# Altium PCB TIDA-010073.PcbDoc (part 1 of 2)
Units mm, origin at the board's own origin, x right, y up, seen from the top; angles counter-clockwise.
Board outline 68.14 x 25.33 mm, 2 copper layers (Top Layer, Bottom Layer), stack 1.575 mm thick; 47 components, 34 nets, 125 pads, 64 vias.
Unrouted connection lines stored in the file: 4.
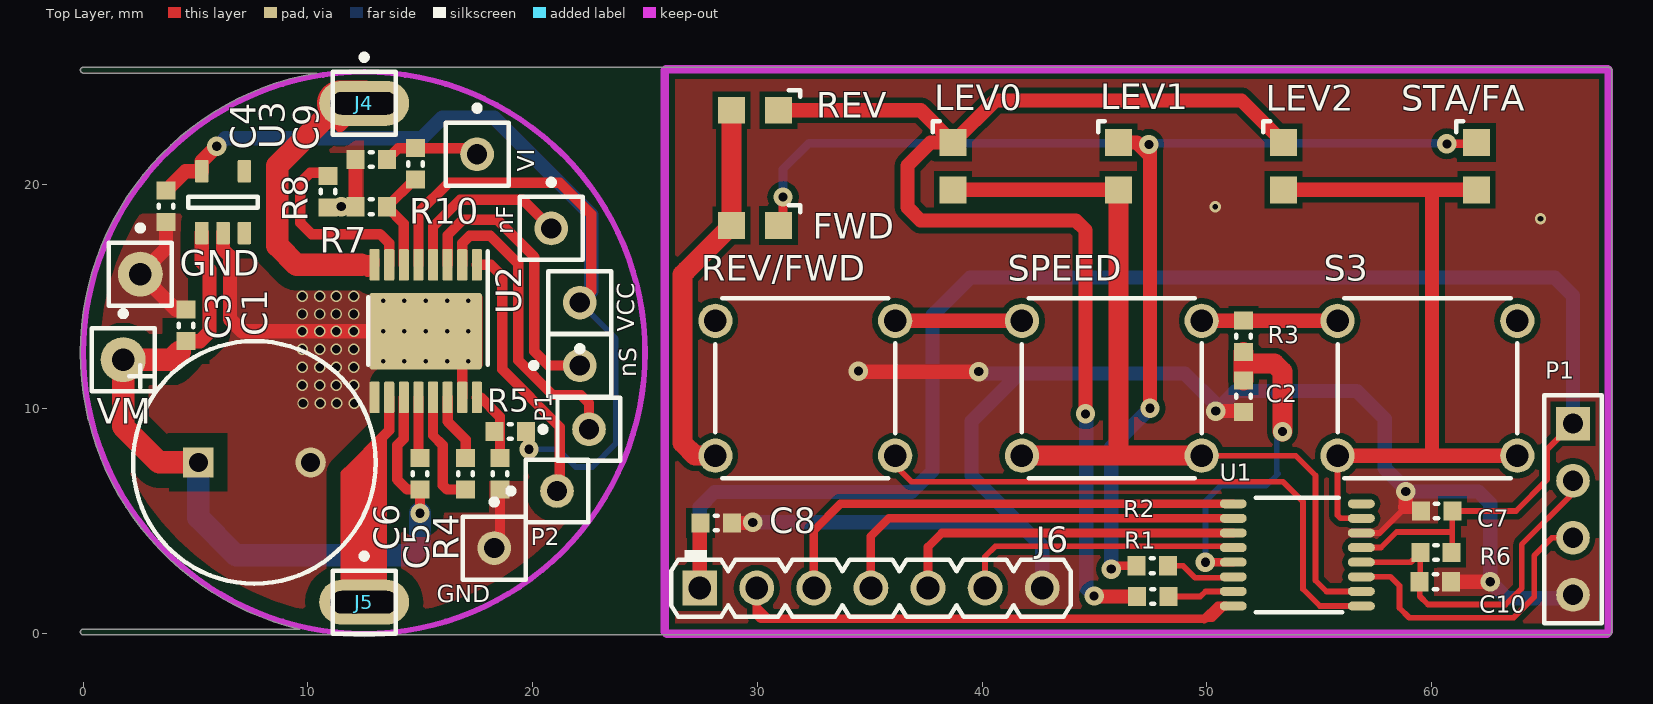
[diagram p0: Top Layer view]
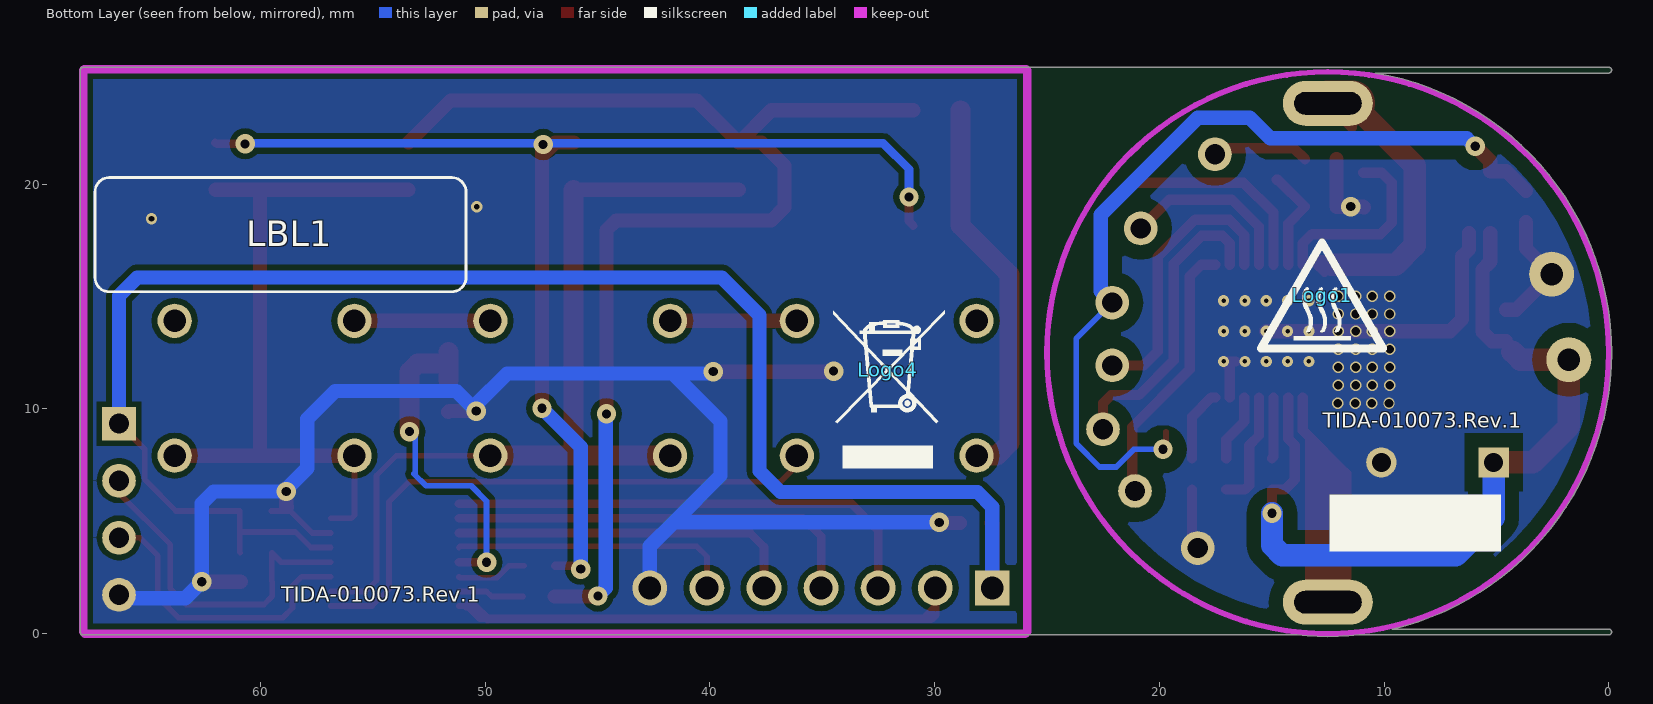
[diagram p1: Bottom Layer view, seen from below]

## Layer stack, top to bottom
Top Solder: solder mask 0.0102, Solder Resist, Dk 3.5
Top Layer: signal copper 0.0356
Dielectric1: core 1.5037, FR-4, Dk 4.8
Bottom Layer: signal copper 0.0356
Bottom Solder: solder mask 0.0102, Solder Resist, Dk 3.5

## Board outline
0,-0.051 cw(c0,0.076) 0,0.204 9.628,0.204 cw(c12.5,12.5) -0.127,12.5 cw(c12.5,12.5) 10.384,24.949 0,24.949 cw(c0,25.076) 0,25.204 67.885,25.204 cw(c67.885,25.076) 68.013,25.076 68.013,0.076 cw(c67.885,0.076) 67.885,-0.051 13.885,-0.051 cw(c12.5,12.5) 12.5,-0.127 cw(c12.5,12.5) 11.115,-0.051

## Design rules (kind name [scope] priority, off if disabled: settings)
AcuteAngle [All] p1: minimum=4.50000000000000E+0001 checktracksonly=FALSE
AssemblyTestPointUsage [All] p1: valid=2
BoardOutlineClearance BoardOutlineClearance_MountingHoles [OnCopper and InComponentClass('Mounting Holes')] p1 off: gap=1.016 ignorepadtopadclearanceinfootprint=FALSE
BoardOutlineClearance BoardOutlineClearance_Poly [OnCopper and IsPoly] p2 off: gap=0.635 ignorepadtopadclearanceinfootprint=FALSE
BoardOutlineClearance [OnCopper and Not InComponentClass('Logo') and not InComponentClass('FiducialMark') and not InRegion(1000,500,4000,800) and not InPoly] p3 off: gap=1.905 ignorepadtopadclearanceinfootprint=FALSE
Clearance Clearance_Keepouts [((IsTrack Or IsArc) And Not InPoly) And IsFree and IsKeepOut vs ((IsTrack Or IsArc) And Not InPoly) And IsFree and IsKeepOut] p1 off: gap=0 ignorepadtopadclearanceinfootprint=FALSE
Clearance Clearance_Poly [InPolygon] p2 off: gap=0.635 ignorepadtopadclearanceinfootprint=FALSE except(0: Arc-Hole Track-Hole SMDPad-Hole THPad-Hole Via-Hole Fill-Hole Poly-Hole Region-Hole Text-Hole)
Clearance Clearance_FiducialMark [IsKeepOut and InComponentClass('FiducialMark') vs IsPad and InComponentClass('FiducialMark')] p3 off: gap=0.381 ignorepadtopadclearanceinfootprint=FALSE
Clearance [All] p4: gap=0.254 ignorepadtopadclearanceinfootprint=FALSE
ComponentClearance ComponentClearance_MountingHoles_FiducialMarks [InComponentClass('Mounting Holes') vs InComponentClass('FiducialMark')] p1: gap=1.27 collisioncheckmode=3 verticalgap=0.254 showdistances=FALSE
ComponentClearance ComponentClearance_Shunt [InComponentClass('Header') vs InComponentClass('Shunt')] p2: gap=0 collisioncheckmode=3 verticalgap=0 showdistances=FALSE
ComponentClearance ComponentClearance_Logo [InComponentClass('Logo')] p3: gap=1.27 collisioncheckmode=3 verticalgap=0.254 showdistances=FALSE
ComponentClearance ComponentClearance_ScrewToNut [(HasFootprint('NY PMS 440 0025 PH')) vs (HasFootprint('Keystone_1902C'))] p4: gap=0.127 collisioncheckmode=3 verticalgap=0.254 showdistances=FALSE
ComponentClearance ComponentClearance_MountingHoles [InComponentClass('Mounting Holes')] p5: gap=6.35 collisioncheckmode=3 verticalgap=2540 showdistances=FALSE
ComponentClearance ComponentClearance_SmallPassives [HasFootprint('0201*') or HasFootprint('0402*') or HasFootprint('0508') or HasFootprint('0603*') or HasFootprint('0612') or HasFootprint('0805*') or HasFootprint('0815*') or HasFootprint('0830*') or HasFootprint('1206*') or HasFootprint('1210*') or HasFootprint('1808*') or HasFootprint('1812*') or HasFootprint('1825*') or HasFootprint('2010*') or HasFootprint('2220*') or HasFootprint('2225*') or HasFootprint('2512*') or HasFootprint('2728*') or HasFootprint('3518*') vs HasFootprint('0201*') or HasFootprint('0402*') or HasFootprint('0508') or HasFootprint('0603*') or HasFootprint('0612') or HasFootprint('0805*') or HasFootprint('0815*') or HasFootprint('0830*') or HasFootprint('1206*') or HasFootprint('1210*') or HasFootprint('1808*') or HasFootprint('1812*') or HasFootprint('1825*') or HasFootprint('2010*') or HasFootprint('2220*') or HasFootprint('2225*') or HasFootprint('2512*') or HasFootprint('2728*') or HasFootprint('3518*')] p6: gap=0.38 collisioncheckmode=3 verticalgap=0.254 showdistances=FALSE
ComponentClearance ComponentClearance_THtoSMT [IsThruComponent vs IsSMTComponent] p7: gap=1.016 collisioncheckmode=3 verticalgap=0.762 showdistances=FALSE
ComponentClearance ComponentClearance_THtoTH [IsThruComponent vs IsThruComponent] p8: gap=0.762 collisioncheckmode=3 verticalgap=0.762 showdistances=FALSE
ComponentClearance [All] p9: gap=0.762 collisioncheckmode=3 verticalgap=0.254 showdistances=FALSE
DiffPairsRouting [All] p1: maxlimit=2.54 minlimit=0.254 mostfreqgap=0.254 toplayer_minwidth=0.381 toplayer_maxwidth=0.381 toplayer_prefwidth=0.381 bottomlayer_minwidth=0.381 bottomlayer_maxwidth=0.381 bottomlayer_prefwidth=0.381 maxuncoupledlength=25.4
FabricationTestPointUsage TestPointUsage [All] p1: valid=2 allowmultiple=FALSE
FabricationTestpoint Testpoint [All] p1: side=3 testpointundercomponent=TRUE minsize=1.016 maxsize=2.54 preferedsize=1.524 minholesize=0 maxholesize=1.016 preferedholesize=0.813 testpointgrid=0.025 allowsidetop=TRUE allowsidebottom=TRUE usegrid=TRUE gridtolerance=0
FanoutControl Fanout_LCC [IsLCC] p1: bgadir=Out bgaviamode=Centered fanoutstyle=Auto fanoutdirection=Alternating viagrid=0.025 // Fanout_LCC (Default Rule)
FanoutControl Fanout_BGA [IsBGA] p2: bgadir=Out bgaviamode=Centered fanoutstyle=Auto fanoutdirection=Alternating viagrid=0.025 // Fanout_BGA (Default Rule)
FanoutControl Fanout_Default [All] p4: bgadir=Out bgaviamode=Centered fanoutstyle=Auto fanoutdirection=Alternating viagrid=0.025 // Fanout_Default (Default Rule)
FanoutControl Fanout_Small [(CompPinCount < 5)] p5: bgadir=Out bgaviamode=Centered fanoutstyle=Auto fanoutdirection=OutThenIn viagrid=0.025 // Fanout_Small (Default Rule)
HoleSize [All] p1: absolutevalues=TRUE maxlimit=6.375 minlimit=0.2 maxpercent=80.000 minpercent=20.000
HoleToHoleClearance [All] p1 off: gap=0.254 allowstackedmicrovias=TRUE
MinimumAnnularRing MinimumAnnularRing_ThermalPadVias [IsVia and InAnyComponent] p1: minimumring=0.15
MinimumAnnularRing [All] p2: minimumring=0.203
MinimumSolderMaskSliver MinimumSolderMaskSliver_Logo [InComponentClass('Logo') vs InComponentClass('Logo')] p1: minsoldermaskwidth=0.018
MinimumSolderMaskSliver [All] p2: minsoldermaskwidth=0.1
PlaneConnect [All] p1: planeconnectstyle=Relief reliefexpansion=0.254 reliefentries=4 reliefconductorwidth=0.254 reliefairgap=0.254
PolygonConnect [All] p1: connectstyle=Direct reliefconductorwidth=0.254 reliefentries=4 polygonreliefangle="90 Angle" airgapwidth=0.254
RoutingVias ThermalPadVias [IsVia and InAnyComponent] p1: holewidth=0.2 width=0.5 viastyle="Through Hole" minholewidth=0.2 minwidth=0.5 maxholewidth=0.33 maxwidth=0.6
RoutingVias [All] p2: holewidth=0.406 width=0.864 viastyle="Through Hole" minholewidth=0.2 minwidth=0.66 maxholewidth=1.016 maxwidth=1.651
SilkToBoardRegionClearance [Not ((IsComment or IsDesignator) And (Hide <> 'False')) and not InRegion(1000,500,4000,800)] p1:
SilkToSilkClearance SilkToSilkClearance_Pb-FreeLogo [(HasFootprint('Pb-Free_Overlay_Medium') OR HasFootprint('Pb-Free_Overlay_Small')) vs (HasFootprint('Pb-Free_Overlay_Medium') OR HasFootprint('Pb-Free_Overlay_Small'))] p1: silktosilkclearance=0
SilkToSilkClearance [All] p2: silktosilkclearance=0.102
SilkToSolderMaskClearance SilkToComponentPadClearance [(IsPad or IsFill or IsRegion) and InAnycomponent] p1: minsilkscreentomaskgap=0.127 clearancetoexposedcopper=TRUE
SilkToSolderMaskClearance "Silk to Solder Mask Opening" [All] p2: minsilkscreentomaskgap=0.102 clearancetoexposedcopper=FALSE
SolderMaskExpansion [All] p1: expansion=0.05
UnRoutedNet [All] p1 off:
UnpouredPolygon [All] p1 off:
Width [All] p1: maxlimit=2.54 minlimit=0.152 preferedwidth=0.254 checkconnectedcopper=TRUE
12 further rules are at their usual default settings.

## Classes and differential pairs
component class Header: J6
component class TIDA-010073_Page1: C1 C2 C3 C4 C5 C6 C7 C8 C9 C10 FWD GND J4 J5 J6 LEV0 LEV1 LEV2 nF nS P1 P2 R1 R2 R3 R4 R6 R7 R8 R10 REV REV/FWD S3 SPEED STA/FA U1 U2 U3 VCC VI VM
component class Label: LBL1
component class TIDA-010073_EVM_Hardware: LBL1 Logo1 Logo4

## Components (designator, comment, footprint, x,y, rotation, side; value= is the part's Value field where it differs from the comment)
C1 "UBT1H101MPD1TD" BT_1000x1250 7.62,7.62 r0 top value=100uF
C2 "C0603X104K8RACTU" 0603L 51.638,10.566 r270 top value=0.1uF
C3 "C1608X7R1H104K080AA" 0603L 4.572,13.716 r90 top value=0.1uF
C4 "GRM188R71A225KE15D" 0603L 3.683,19.013 r270 top value=2.2uF
C5 "885012206091" 0603L 17.018,7.112 r90 top value=0.022uF
C6 "C1608X7R1H104K080AA" 0603L 14.986,7.112 r90 top value=0.1uF
C7 "C1608X7R1H104K080AA" 0603L 60.223,5.461 r180 top value=0.1uF
C8 "885012206026" 0603L 28.169,4.928 r0 top value=1uF
C9 "C1608X7R1H104K080AA" 0603L 12.813,21.107 r180 top value=0.1uF
C10 "C0603C471K5RACTU" 0603L 60.173,2.311 r0 top value=470pF
FWD "SM0805GCL" SM0805_Green 29.896,18.161 r0 top value=Green (schematic designator D2)
GND "GND" PIN1#1 2.54,16.002 r0 top (schematic designator J3)
GND "VM" PIN1#2 18.288,3.81 r0 top (schematic designator J12)
J4 "OUT1" PIN1#3 12.5,23.6 r0 top
J5 "OUT2" PIN1#3 12.5,1.4 r0 top
J6 "PBC07SFAN" Sullins_xxC07SFAN 35.052,2.032 r0 top
LBL1 "THT-14-423-10" Label_650x200 59.106,17.755 r180 bottom
LEV0 "SM0805GCL" SM0805_Green 38.71,20.803 r90 top value=Green (schematic designator D3)
LEV1 "SM0805GCL" SM0805_Green 46.063,20.803 r90 top value=Green (schematic designator D4)
LEV2 "SM0805GCL" SM0805_Green 53.416,20.803 r90 top value=Green (schematic designator D5)
Logo1 "CAUTION HOT SURFACE" IEC_HotSurface_Small 12.755,15.062 r180 bottom (schematic designator LOGO1)
Logo4 "WEEE logo" WEEE_Minimum 32.078,11.735 r180 bottom
nF "VM" PIN1#2 20.828,18.034 r0 top (schematic designator J9)
nS "VM" PIN1#2 22.098,11.938 r90 top (schematic designator J8)
P1 "VM" PIN1#2 22.504,9.093 r90 top (schematic designator J11)
P1 "Header 4" HDR1X4 66.294,9.347 r270 top
P2 "VM" PIN1#2 21.082,6.35 r90 top (schematic designator J10)
R1 "CRCW0603330RJNEA" 0603L 47.6,1.651 r180 top value=330
R2 "CRCW0603330RJNEA" 0603L 47.574,3.023 r180 top value=330
R3 "CRCW06031K00JNEA" 0603L 51.638,13.233 r270 top value=1.0k
R4 "ERJ-3GEY0R00V" 0603L 18.542,7.112 r90 top value=0
R5 "ERJ-3GEY0R00V" 0603L 18.999,8.992 r180 top value=0
R6 "CRCW060347K0JNEA" 0603L 60.198,3.607 r180 top value=47k
R7 "ERJ-3GEY0R00V" 0603L 12.816,18.999 r0 top value=0
R8 "ERJ-3GEY0R00V" 0603L 10.897,19.674 r90 top value=0
R10 "RC0603JR-072K2L" 0603L 14.783,20.904 r90 top value=2.2k
REV "SM0805GCL" SM0805_Green 29.896,23.292 r0 top value=Green (schematic designator D1)
REV/FWD "ESE-20C341" SW_ESE20C3 32.131,10.922 r0 top (schematic designator S1)
S3 "ESE-20C341" SW_ESE20C3 59.817,10.922 r0 top
SPEED "ESE-20C341" SW_ESE20C3 45.771,10.922 r0 top (schematic designator S2)
STA/FA "SM0805GCL" SM0805_Green 62.001,20.803 r90 top value=Green (schematic designator D6)
U1 "MSP430FR2111IPW16R" PW0016A_L 54.026,3.505 r180 top
U2 "DRV8876PWPR" PWP0016J_N 15.24,13.462 r270 top
U3 "TPS70933DBVR" DBV0005A_N 6.223,19.202 r90 top
VCC "VM" PIN1#2 22.098,14.732 r180 top (schematic designator J1)
VI "VM" PIN1#2 17.526,21.336 r0 top (schematic designator J7)
VM "VM" PIN1#1 1.778,12.192 r0 top (schematic designator J2)

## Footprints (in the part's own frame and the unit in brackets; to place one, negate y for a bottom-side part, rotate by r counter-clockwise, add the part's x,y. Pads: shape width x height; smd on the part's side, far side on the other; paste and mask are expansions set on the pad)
0603L [mm] "0603 from SM-752 data"
  rect 0.8x0.85 smd: 1(-0.7,0) 2(0.7,0)
  silkscreen extent -0.07,-0.33 0.07,0.33, body extent -0.87,-0.47 0.87,0.47, height 1
BT_1000x1250 [mm] "Nichicon"
  rect 1.35x1.35 hole 0.85 paste+0: 1(-2.5,0)
  round 1.35 hole 0.85 paste+0: 2(2.5,0)
  silkscreen extent -5.58,-5.4 5.4,5.4, body extent -5.36,-5.39 5.39,5.39, height 14.51
DBV0005A_N [mm] "SOT23, 5-Leads, Body 2.9x1.6mm, Pitch 0.95mm, Lead Span 2.8mm, IPC Medium Density"
  rrect17% 1x0.6 smd: 1(-1.375,0.95) 2(-1.375,0) 3(-1.375,-0.95) 4(1.375,-0.95) 5(1.375,0.95)
  silkscreen extent -0.25,-1.55 0.25,1.55, body extent -1.42,-1.46 1.42,1.46, height 1.09
HDR1X4 [mm] "Connector; Header; 4 Position"
  rect 1.5x1.5 hole 0.9: 1(0,0)
  round 1.5 hole 0.9: 2(2.54,0) 3(5.08,0) 4(7.62,0)
  silkscreen extent -1.27,-1.27 8.89,1.27
IEC_HotSurface_Small [mm]
  silkscreen extent -2.72,-2.36 2.72,2.35
Label_650x200 [mil] "Thermal Transfer Label"
  round 1 on Mech14: 0(0,0)
  silkscreen extent -325,-100 325,100, body extent -325,-100 325,100, height 1
PIN1#1 [mm] "Connector; Plug"
  round 2 hole 1: 1(0,0)
  silkscreen extent -1.4,-1.4 1.4,2.17
PIN1#2 [mm] "Connector; Plug"
  round 1.5 hole 0.9: 1(0,0)
  silkscreen extent -1.4,-1.4 1.4,2.17
PIN1#3 [mm] "Connector; Plug"
  oval 4x2 hole 1 slot 3 at 0 deg: 1(0,0)
  silkscreen extent -1.4,-1.4 1.4,2.17
PW0016A_L [mm] "TSOP, 16-Leads, Body 5x4.4mm, Pitch 0.65mm, IPC High Density"
  oval 1.2x0.4 smd: 1(-2.85,2.275) 2(-2.85,1.625) 3(-2.85,0.975) 4(-2.85,0.325) 5(-2.85,-0.325) 6(-2.85,-0.975) 7(-2.85,-1.625) 8(-2.85,-2.275) 9(2.85,-2.275) 10(2.85,-1.625) 11(2.85,-0.975) 12(2.85,-0.325) 13(2.85,0.325) 14(2.85,0.975) 15(2.85,1.625) 16(2.85,2.275)
  silkscreen extent -2,-2.55 1.85,2.55, body extent -3.21,-2.5 3.21,2.5, height 1
PWP0016J_N [mm] "TSOP, 16-Leads, Body 5x4.4mm, Pitch 0.65mm, Exposed Pad, IPC Medium Density"
  rrect22% 1.4x0.45 smd: 1(-2.95,2.275) 2(-2.95,1.625) 3(-2.95,0.975) 4(-2.95,0.325) 5(-2.95,-0.325) 6(-2.95,-0.975) 7(-2.95,-1.625) 8(-2.95,-2.275) 9(2.95,-2.275) 10(2.95,-1.625) 11(2.95,-0.975) 12(2.95,-0.325) 13(2.95,0.325) 14(2.95,0.975) 15(2.95,1.625) 16(2.95,2.275)
  rrect6% 3.4x5 smd paste-1.7 mask-1.7: 17(0,0)
  rrect4% 2.46x3.55 on Top Paste: 17(0,0)
  rrect4% 2.46x3.55 on Top Solder: 17(0,0)
  silkscreen extent -3.55,-2.55 1.5,2.75, body extent -3.2,-2.5 3.2,2.5, height 1.13
SM0805_Green [mm] "Bivar"
  rect 1.2x1.2 smd: 1(-1.05,0) 2(1.05,0)
  silkscreen extent 1.5,0.6 2,0.9, body extent -1.13,-0.75 1.13,0.75, height 1.07
Sullins_xxC07SFAN [mm] "Header, 2.54 mm, 7x1, TH"
  rect 1.55x1.55 hole 1.016: 1(-7.62,0)
  round 1.55 hole 1.016: 2(-5.08,0) 3(-2.54,0) 4(0,0) 5(2.54,0) 6(5.08,0) 7(7.62,0)
  silkscreen extent -8.89,-1.28 8.89,1.7, body extent -8.89,-1.27 8.89,1.27, height 10.62
SW_ESE20C3 [mm] "Panasonic recommended land pattern  00 Sept 2010"
  round 1.524 hole 1: A(-4,3) B(-4,-3) C(4,3) D(4,-3)
  silkscreen extent -4,-4 4,4, body extent -3.9,-3.95 3.9,3.95, height 12.5
WEEE_Minimum [mm] "WEEElie bin"
  silkscreen extent -2.42,-4.38 2.52,2.65

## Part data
C1: library part CMP-0009918-2, "CAP, AL, 100 uF, 50 V, +/- 20%, TH", Cap_Case=10x12.5mm, Manufacturer=Nichicon, Supplier Part Number 1=493-4508-1-ND, Tolerance_%=20%, Value1=Unknown, Value2=50V, ValueDisplayed=100uF
C2: "CAP, CERM, 0.1 ¦ÌF, 10 V,+/- 10%, X7R, 0603", Cap_Case=0603, Manufacturer=Kemet, Supplier Part Number 1=399-5343-1-ND, TempCo=X7R, Tolerance_%=10, Value2=10V, ValueDisplayed=0.1µF
C3 C6 C7 C9: library part CMP-0007044-5, "CAP, CERM, 0.1 uF, 50 V, +/- 10%, X7R, 0603", Cap_Case=0603, Manufacturer=TDK, Supplier Part Number 1=445-1314-1-ND, TempCo=X7R, Tolerance_%=10%, Value1="0.0296 ohm", Value2=50V, ValueDisplayed=0.1uF
C4: "CAP, CERM, 2.2 ¦ÌF, 10 V,+/- 10%, X7R, 0603", Cap_Case=0603, Manufacturer=MuRata, Supplier Part Number 1=490-4520-1-ND, TempCo=X7R, Tolerance_%=10, Value1="0.009 ohm", Value2=10V, ValueDisplayed=2.2µF
C5: library part CMP-0006836-4, "CAP, CERM, 0.022 uF, 50 V, +/- 10%, X7R, 0603", Cap_Case=0603, Manufacturer="Wurth Elektronik", TempCo=X7R, Tolerance_%=10%, Value1=Unknown, Value2=50V, ValueDisplayed=0.022uF
C8: library part CMP-0064932-4, "CAP, CERM, 1 uF, 10 V,+/- 10%, X7R, 0603", Cap_Case=0603, Manufacturer="Wurth Elektronik", Supplier Part Number 1=732-7945-1-ND, TempCo=X7R, Tolerance_%=10%, Value1=Unknown, Value2=10V, ValueDisplayed=1uF
C10: "CAP, CERM, 470 pF, 50 V,+/- 10%, X7R, 0603", Cap_Case=0603, Manufacturer=Kemet, Supplier Part Number 1=399-1075-1-ND, TempCo=X7R, Tolerance_%=10, Value2=50V, ValueDisplayed=470pF
FWD LEV0 LEV1 LEV2 REV STA/FA: library part CMP-0002859-2, "LED, Green, SMD", Color=green, Manufacturer=Bivar, Value1=W, Value2=1.9V
GND GND J4 J5 nF nS P1 P2 VCC VI VM: library part Socket, "Socket"
J6: library part CMP-0054600-1, "Header, 2.54 mm, Gold, 7x1, TH", Color=Black, Current_A=3A, Manufacturer="Sullins Connector Solutions", Supplier Part Number 1=S1211E-07-ND, Voltage_V=1.8kV
LBL1: library part CMP-0003625-1, "Thermal Transfer Printable Labels, 0.650\" W x 0.200\" H - 10,000 per roll", Manufacturer=Brady, Supplier Part Number 1=97C5133
Logo1: library part CMP-0074837-1, "IEC 61010-1 Hot Surface Warning"
Logo4: library part CMP-0074769-1
P1: "Header, 4-Pin"
R1 R2: "RES, 330, 5%, 0.1 W, 0603", Manufacturer=Vishay-Dale, Power_W=0.1, Supplier Part Number 1=541-330GCT-ND, TempCo="200 ppm/C", Tolerance_%=5, Value1=5%, Value2=0.1W, Value_Code=330R, ValueDisplayed=330
R3: "RES, 1.0 k, 5%, 0.1 W, 0603", Manufacturer=Vishay-Dale, Power_W=0.1, Supplier Part Number 1=541-1.0KGCT-ND, TempCo="200 ppm/C", Tolerance_%=5, Value1=5%, Value2=0.1W, Value_Code=1k00, ValueDisplayed=1.0k
R4 R5 R8: library part CMP-0025874-3, "RES, 0, 5%, 0.1 W, 0603", Manufacturer=Panasonic, Power_W=100mW, Supplier Part Number 1=P0.0GCT-ND, TempCo="600 ppm/C", Tolerance_%=5%, Value2=0.1W, Value_Code=0000, ValueDisplayed=0
R6: library part CMP-0025814-4, "RES, 47 k, 5%, 0.1 W, AEC-Q200 Grade 0, 0603", Manufacturer=Vishay-Dale, Power_W=100mW, Supplier Part Number 1=541-47KGCT-ND, TempCo="200 ppm/C", Tolerance_%=5%, Value2=0.1W, Value_Code=47k0, ValueDisplayed=47k
R7: library part CMP-0025874-3, "RES, 0, 5%, 0.1 W, 0603", Manufacturer=Panasonic, Power_W=100mW, Supplier Part Number 1=P0.0GCT-ND, TempCo="600 ppm/C", Tolerance_%=5%, Value2=0.1W, Value_Code=0000, ValueDisplayed=1.5K
R10: "RES, 2.2 k, 5%, 0.1 W, 0603", Manufacturer="Yageo America", Power_W=0.1, Supplier Part Number 1=311-2.2KGRCT-ND, TempCo="100 ppm/C", Tolerance_%=5, Value1=5%, Value2=0.1W, Value_Code=2k20, ValueDisplayed=2.2k
REV/FWD S3 SPEED: library part CMP-0002112-2, "Switch, Push, SPST-NO, 0.1A, 14V", CurrentRating_mA=100A, Manufacturer=Panasonic, Supplier Part Number 1=P12348S-ND
U1: library part CMP-0076600-1, "16 MHz Ultra-Low-Power Microcontroller With 4 KB FRAM, 1 KB SRAM, 12 IO, 8 ch ADC10, PW0016A (TSSOP-16)", Alternate Manufacturer="Texas Instruments", Alternate PartNumber=MSP430FR2111IPW16
U2: library part CMP-0079885-2, "H-Bridge Motor Drivers With Integrated Current Sense and Regulation, PWP0016J (TSSOP-16)", Alternate Manufacturer="Texas Instruments", Alternate PartNumber=DRV8876PWP
U3: library part CMP-0073793-1, "150-mA, 30-V, Ultra-Low IQ, Wide Input Low-Dropout Regulator with Reverse Current Protection, DBV0005A (SOT-23-5)", Alternate Manufacturer="Texas Instruments", Alternate PartNumber=TPS70933DBVT

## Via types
v1: diameter 0.508, hole 0.381, Top Layer to Bottom Layer, 28 vias
v2: diameter 0.864, hole 0.406, Top Layer to Bottom Layer, 19 vias
v3: diameter 0.5, hole 0.2, Top Layer to Bottom Layer, tented both sides, 12 vias
v4: diameter 0.5, hole 0.2, Top Layer to Bottom Layer, 3 vias
v5: diameter 0.508, hole 0.254, Top Layer to Bottom Layer, 2 vias

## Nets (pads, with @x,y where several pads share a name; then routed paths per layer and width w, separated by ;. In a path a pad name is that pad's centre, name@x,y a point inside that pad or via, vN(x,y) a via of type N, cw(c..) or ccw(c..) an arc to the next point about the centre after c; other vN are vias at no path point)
CPH: C5.1 U2.13 | length 5.2
  Top Layer w0.457: U2.13@15.565,10.512 15.565,8.819 16.002,8.382 16.002,6.604 16.194,6.412 C5.1@17.018,6.412
CPL: C5.2 U2.14 | length 3
  Top Layer w0.457: U2.14@16.215,10.512 16.215,9.439 17.018,8.636 C5.2@17.018,7.812
GND: C1.2 C3.2 C4.2 C9.2 GND.1 R4.1 R7.1 R8.1 U2.9 U2.15 U2.17@15.24,13.462 U3.2 | length 26.3
  Top Layer w0.457: U2.17@16.59,12.112 v3(17.14,12.112) 16.865,11.837 U2.15@16.865,10.512 ; GND.1@18.542,4.064 R4.1@18.542,6.412
  Top Layer w0.635: C4.2@3.683,18.313 3.683,17.145 GND.1@2.54,16.002 4.126,14.416 C3.2@4.572,14.416 ; U3.2@6.223,17.827 6.223,17.094 6.528,16.789 6.528,13.995 7.061,13.462 v1(9.754,13.462) v1(10.516,13.462) v1(11.252,13.462) v1(12.04,13.462) v3(13.34,13.462) v4(14.29,13.462) v4(15.24,13.462) ; R8.1@10.897,18.974 10.925,19.002 v2(11.481,19.002) 12.113,19.002 C9.2@12.113,21.107
  other v1: 9.779,10.262 10.541,10.262 11.278,10.262 12.065,10.262 9.754,11.049 10.516,11.049 11.252,11.049 12.04,11.049 9.754,11.862 10.516,11.862 11.252,11.862 12.04,11.862 9.754,12.649 10.516,12.649 11.252,12.649 12.04,12.649 9.754,14.224 10.516,14.224 11.252,14.224 12.04,14.224 9.754,15.011 10.516,15.011 11.252,15.011 12.04,15.011
  other v3: 13.34,12.112 14.29,12.112 15.24,12.112 16.19,12.112 17.14,13.462 13.34,14.812 14.29,14.812 15.24,14.812 16.19,14.812 17.14,14.812
  other v4: 16.19,13.462
GND1: C2.2 C7.2 C8.2 C10.2 J6.7 P1.4 U1.6 | length 71.7
  Top Layer w0.254: U1.6@56.876,4.48 57.693,4.48 58.674,5.461 C7.2@59.523,5.461
  Top Layer w0.635: C8.2@28.869,4.928 29.82,4.928 v2(29.794,4.953) ; v2(34.493,11.684) 34.519,11.659 v2(39.853,11.659) ; v2(50.394,9.906) 51.599,9.906 C2.2@51.638,9.866 ; 58.826,5.639 58.852,5.664 v2(58.852,6.325) ; C10.2@60.873,2.311 v2(62.611,2.311)
  Bottom Layer w0.635: v2(29.794,4.953) 41.529,4.953 41.567,4.991 ; v2(39.853,11.659) 39.853,11.582 41.656,11.582 ; J6.7@42.672,2.032 42.672,3.886 41.567,4.991 ; P1.4@66.294,1.727 66.142,1.575 63.348,1.575 v2(62.611,2.311) 62.611,5.791 62.078,6.325 v2(58.852,6.325) 58.852,6.426 57.912,7.366 57.912,9.55 56.667,10.795 51.283,10.795 v2@50.419,9.931 ; 41.567,4.991 39.522,7.036 39.522,9.449 41.656,11.582 ; 41.656,11.582 49.022,11.582 50.419,10.185 v2@50.419,9.931 ; v2@50.419,9.931 v2(50.394,9.906) 50.419,9.906 v2@50.419,9.931
  other v5: 64.846,18.466 50.368,18.999
IMODE: R8.2 U2.7 | length 8.5
  Top Layer w0.457: R8.2@10.922,20.512 10.098,20.512 9.652,20.066 9.652,18.288 10.16,17.78 13.208,17.78 13.615,17.373 U2.7@13.615,16.412
Line0_MCU: R1.1 U1.15 | length 3
  Top Layer w0.254: R1.1@48.3,1.651 49.708,1.651 49.937,1.88 U1.15@51.176,1.88
Line1_MCU: R2.1 U1.14 | length 3.1
  Top Layer w0.254: R2.1@48.274,3.023 48.946,3.023 49.479,2.489 51.135,2.489 U1.14@51.176,2.53
Line2_MCU: C2.1 R3.2 U1.13 | length 15.5
  Top Layer w0.254: v2(49.936,3.175) v2@49.942,3.18
  Top Layer w0.381: v2@49.942,3.18 U1.13@51.176,3.18
  Top Layer w0.889: C2.1@51.638,11.266 51.638,12.014 ; R3.2@51.638,12.533 51.638,12.014 ; v2(53.365,8.992) 53.365,11.659 53.01,12.014 51.638,12.014
  Bottom Layer w0.254: v2(49.936,3.175) 49.936,5.893 50.622,6.579 52.629,6.579 53.162,7.112 53.111,7.163 53.111,8.738 v2(53.365,8.992)
NetC6_2: C6.2 U2.12 | length 2.7
  Top Layer w0.457: U2.12@14.915,10.512 14.915,7.883 C6.2@14.986,7.812
NetD1_2: LEV0.2 LEV2.2 R1.2 REV.2 | length 55.7
  Top Layer w0.635: REV.2@30.946,23.292 37.27,23.292 LEV0.2@38.71,21.853 ; v2(44.602,9.779) 44.602,17.958 44.171,18.39 37.262,18.39 36.678,18.974 36.678,20.828 37.702,21.853 LEV0.2@38.71,21.853 ; v2(44.983,1.676) 44.983,1.651 R1.2@46.9,1.651 ; LEV2.2@53.416,21.853 51.545,23.724 40.581,23.724 LEV0.2@38.71,21.853
  Bottom Layer w0.635: v2(44.602,9.779) 44.628,9.754 44.628,2.032 v2(44.983,1.676)
NetD2_2: FWD.2 LEV1.2 R2.2 STA/FA.2 | length 56.5
  Top Layer w0.381: FWD.2@30.946,18.161 31.14,18.356 v2(31.14,19.431) ; v2(45.745,2.87) 45.796,2.87 45.949,3.023 R2.2@46.874,3.023 ; v2(60.681,21.793) 61.942,21.793 STA/FA.2@62.001,21.853
  Top Layer w0.635: LEV1.2@46.063,21.853 46.88,21.853 47.473,21.26 ; v2(47.422,21.768) 47.473,21.768 47.473,21.26 ; v2(47.473,10.033) 47.473,21.26
  Bottom Layer w0.381: v2(31.14,19.431) 31.14,20.676 32.283,21.819 60.655,21.819 v2(60.681,21.793)
  Bottom Layer w0.635: v2(45.745,2.87) 45.745,8.306 v2(47.473,10.033)
NetR3_1: R3.1 REV/FWD.A REV/FWD.C S3.A S3.C SPEED.A SPEED.C | length 11.7
  Top Layer w0.635: REV/FWD.C@36.131,13.922 SPEED.A@41.771,13.922 ; SPEED.C@49.771,13.922 S3.A@55.817,13.922
nFAULT: nF.1 U2.4 | length 8
  Top Layer w0.457: U2.4@15.565,16.412 15.565,18.105 16.764,19.304 19.558,19.304 nF.1@20.828,18.034
nFAULT_MCU: J6.4 U1.10 | length 18.8
  Top Layer w0.381: J6.4@35.052,2.032 35.052,4.343 35.839,5.13 U1.10@51.176,5.13
nSLEEP: nS.1 U2.3 | length 12.6
  Top Layer w0.457: U2.3@16.215,16.412 16.215,17.739 16.891,18.415 18.415,18.415 20.066,16.764 20.066,12.57 20.698,11.938 nS.1@22.098,11.938
nSLEEP_MCU: J6.3 U1.9 | length 21.7
  Top Layer w0.381: J6.3@32.512,2.032 32.512,4.597 33.695,5.78 U1.9@51.176,5.78
OUT1: J4.1 U2.8 | length 16.5
  Top Layer w0.457: 11.43,22.53 J4.1@12.5,23.6 ; 12.374,16.372 12.649,16.096 U2.8@12.965,16.412 ; U2.8@12.965,16.412 12.374,16.412 12.588,16.626 12.965,16.626 U2.8@12.965,16.412
  Top Layer w1: J4.1@11.408,23.6 8.636,20.828 8.636,17.272 9.496,16.412 12.374,16.412
  Top Layer w2.032: J4.1@11.408,23.6 J4.1@12.5,23.6
OUT2: J5.1 U2.10 | length 36
  Top Layer w0.457: J5.1@11.684,1.27 11.684,7.112 11.963,7.391 ; J5.1@11.963,1.937 11.963,7.391 ; J5.1@12.408,1.492 12.408,7.836 ; J5.1@12.5,1.4 J5.1@12.865,1.765 ; U2.10@13.615,10.512 13.615,9.043 13.284,8.712 ; 11.963,7.391 12.408,7.836 ; 12.408,7.836 12.865,8.293 ; J5.1@12.865,1.765 12.865,8.293 ; J5.1@12.865,1.765 13.284,2.184 13.284,8.712 ; 12.865,8.293 13.284,8.712
PMODE: R4.2 R5.2 U2.16 | length 3.2
  Top Layer w0.457: U2.16@17.515,10.512 17.688,10.512 18.542,9.658 R4.2@18.542,7.812
PWM1: P2.1 U2.1 | length 12
  Top Layer w0.457: U2.1@17.515,16.412 18.132,16.412 18.644,15.9 18.644,11.76 21.209,9.195 21.209,6.477 P2.1@21.082,6.35
PWM1_MCU: J6.5 U1.11 | length 15.7
  Top Layer w0.381: J6.5@37.592,2.032 37.592,3.861 38.211,4.48 U1.11@51.176,4.48
PWM2: P1.1@22.504,9.093 U2.2 | length 13.5
  Top Layer w0.457: U2.2@16.865,16.412 16.865,17.373 17.196,17.704 18.12,17.704 19.355,16.469 19.355,12.167 20.904,10.617 22.149,10.617 22.504,10.262 P1.1@22.504,9.093
PWM2_MCU: J6.6 U1.12 | length 12.7
  Top Layer w0.254: J6.6@40.132,2.032 40.132,3.429 40.589,3.886 51.12,3.886 U1.12@51.176,3.83
SBWTCK: P1.3 U1.3 | length 13.3
  Top Layer w0.254: U1.3@56.876,2.53 58.176,2.53 58.572,2.134 58.572,1.143 59.004,0.711 63.652,0.711 64.567,1.626 64.567,3.48 65.354,4.267 P1.3@66.294,4.267
SBWTDIO: C10.1 P1.2 R6.2 U1.4 | length 15.5
  Top Layer w0.254: U1.4@56.876,3.18 59.071,3.18 R6.2@59.498,3.607 59.498,2.337 C10.1@59.473,2.311 59.473,1.665 59.842,1.295 63.297,1.295 64.008,2.007 64.008,3.962 66.294,6.248 P1.2@66.294,6.807
Seg0_MCU: FWD.1 REV.1 REV/FWD.B REV/FWD.D U1.1 | length 50.6
  Top Layer w0.254: 26.848,9.205 26.848,16.163 ; REV/FWD.D@35.69,7.922 36.855,6.756 53.391,6.756 54.28,5.867 54.28,1.981 55.031,1.23 U1.1@56.876,1.23
  Top Layer w0.889: REV/FWD.B@28.131,7.922 27.232,7.922 26.67,8.484 26.67,15.985 26.848,16.163 FWD.1@28.846,18.161 REV.1@28.846,23.292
